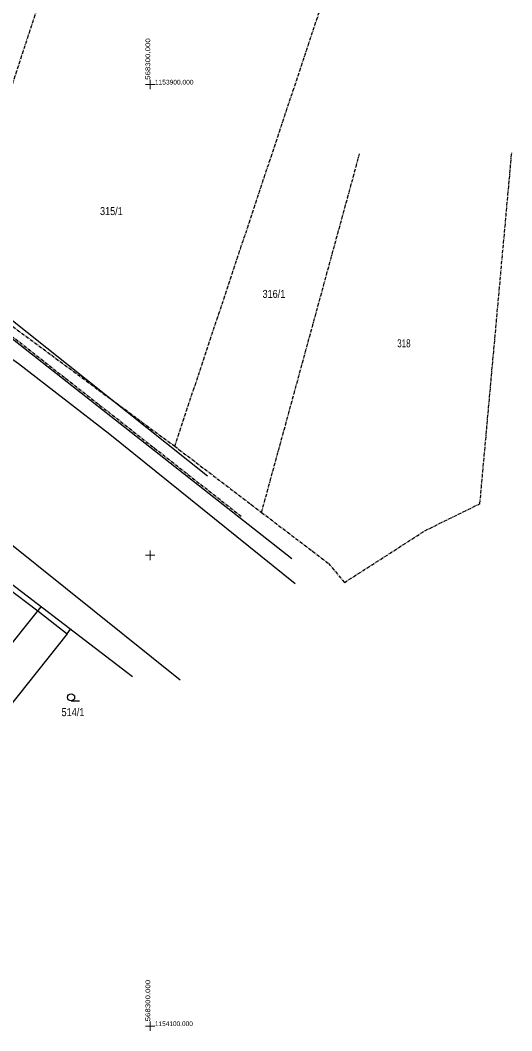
# Model space of a CAD drawing. Extents: x -568530 to -568223, y -1154101 to -1153740.
# Drawn here: x -568327.6 to -568223.2, y -1154101 to -1153886.3 of the extents above; entities that cross this region are included whole.
import ezdxf

# ---------------------------------------------------------------- set-up
doc = ezdxf.new("R2010")
doc.units = 0
doc.header["$LTSCALE"] = 0.14
doc.linetypes.add('DOT_DASHED', pattern=[7.7, 5, -1.2, 0.3, -1.2])
for name, color, linetype, lineweight in [('1', 7, 'Continuous', 25), ('25', 7, 'Continuous', 13), ('4', 7, 'Continuous', 25), ('6', 7, 'DOT_DASHED', 25), ('61', 7, 'Continuous', 13)]:
    doc.layers.add(name, color=color, linetype=linetype, lineweight=lineweight)
doc.layers.add('18', color=7, linetype='Continuous')
doc.layers.add('20', color=7, linetype='Continuous')

msp = doc.modelspace()

# ---------------------------------------------------------------- linework, layer by layer
at = {"layer": '1'}
for p, q in [((-568350.83, -1154045.34), (-568323.15, -1154010.95)), ((-568317.63, -1154016.68), (-568316.92, -1154015.72))]:
    msp.add_line(p, q, dxfattribs=at)
for points in [[(-568393.92, -1153911.77), (-568368.85, -1153922.7), (-568351.96, -1153932.04), (-568287.81, -1153983.13)], [(-568397.85, -1153916.62), (-568382.3, -1153920.09), (-568354.17, -1153934.45), (-568269.88, -1154000.68)], [(-568381.21, -1153967.57), (-568365.54, -1153978.53), (-568303.79, -1154025.76)], [(-568317.63, -1154016.68), (-568344.8, -1154050.79), (-568350.83, -1154045.34)]]:
    msp.add_lwpolyline(points, dxfattribs=at)
at = {"layer": '25', "lineweight": 25}
msp.add_line((-568316.8, -1154030.92), (-568315.05, -1154030.92), dxfattribs=at)
msp.add_circle((-568316.8, -1154030.17), 0.75, dxfattribs=at)
at = {"layer": '4'}
for points in [[(-568416.66, -1153938.36), (-568411.09, -1153926.18), (-568408.89, -1153922.6), (-568403.83, -1153916.49), (-568364.99, -1153940.47), (-568354.7, -1153940.43), (-568327.96, -1153959.28), (-568308.58, -1153974.27), (-568269.22, -1154006.01)], [(-568416.35, -1153942.92), (-568411.96, -1153940.51), (-568386.96, -1153956.01), (-568354.94, -1153977.29), (-568293.66, -1154026.45)], [(-568366.02, -1153979.11), (-568356.52, -1153986.02), (-568349.5, -1153991.27), (-568342.94, -1153996.41), (-568337.12, -1154000.99), (-568330.58, -1154006.67), (-568323.84, -1154011.81), (-568317.63, -1154016.68)]]:
    msp.add_lwpolyline(points, dxfattribs=at)
at = {"layer": '6'}
for p, q in [((-568294.79, -1153976.84), (-568248.75, -1153838.56)), ((-568353.63, -1153934.41), (-568280.65, -1153991.71)), ((-568342.85, -1153941.3), (-568294.79, -1153976.84))]:
    msp.add_line(p, q, dxfattribs=at)
for points in [[(-568292.75, -1153788.12), (-568342.85, -1153941.3), (-568385.34, -1153912.52), (-568390.25, -1153908.12)], [(-568294.79, -1153976.84), (-568276.34, -1153990.89), (-568255.52, -1153914.72)], [(-568276.34, -1153990.89), (-568262.12, -1154001.72), (-568258.73, -1154005.78), (-568241.64, -1153994.78), (-568229.96, -1153989.03), (-568223.19, -1153914.39)]]:
    msp.add_lwpolyline(points, dxfattribs=at)
at = {"layer": '61'}
for p, q in [((-568301, -1153900), (-568299, -1153900)), ((-568300, -1153899), (-568300, -1153901)), ((-568300, -1153999), (-568300, -1154001)), ((-568300, -1153999), (-568300, -1154001)), ((-568301, -1154000), (-568299, -1154000)), ((-568301, -1154000), (-568299, -1154000)), ((-568301, -1154100), (-568299, -1154100)), ((-568300, -1154099), (-568300, -1154101))]:
    msp.add_line(p, q, dxfattribs=at)

# ---------------------------------------------------------------- texts
at = {"layer": '18', "width": 0.85}
msp.add_text('514/1', height=1.7, dxfattribs=at).set_placement((-568318.83, -1154034.17))
at = {"layer": '20'}
for s, width, p in [('315/1', 0.85, (-568310.66, -1153927.73)), ('316/1', 0.85, (-568276.14, -1153945.33)), ('318', 0.75, (-568247.53, -1153955.82))]:
    msp.add_text(s, height=1.7, dxfattribs=dict(at, width=width)).set_placement(p)
at = {"layer": '61', "width": 1.25}
for p in [(-568300, -1153899), (-568300, -1154099)]:
    msp.add_text('568300.000', height=1, rotation=90, dxfattribs=at).set_placement(p)
at = {"layer": '61', "width": 1.05}
msp.add_text('1153900.000', height=1, dxfattribs=at).set_placement((-568299, -1153900))
at = {"layer": '61'}
msp.add_text('1154100.000', height=1, dxfattribs=at).set_placement((-568299, -1154100))

doc.saveas('drawing.dxf')
